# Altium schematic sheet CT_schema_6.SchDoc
size 350 x 348 mm
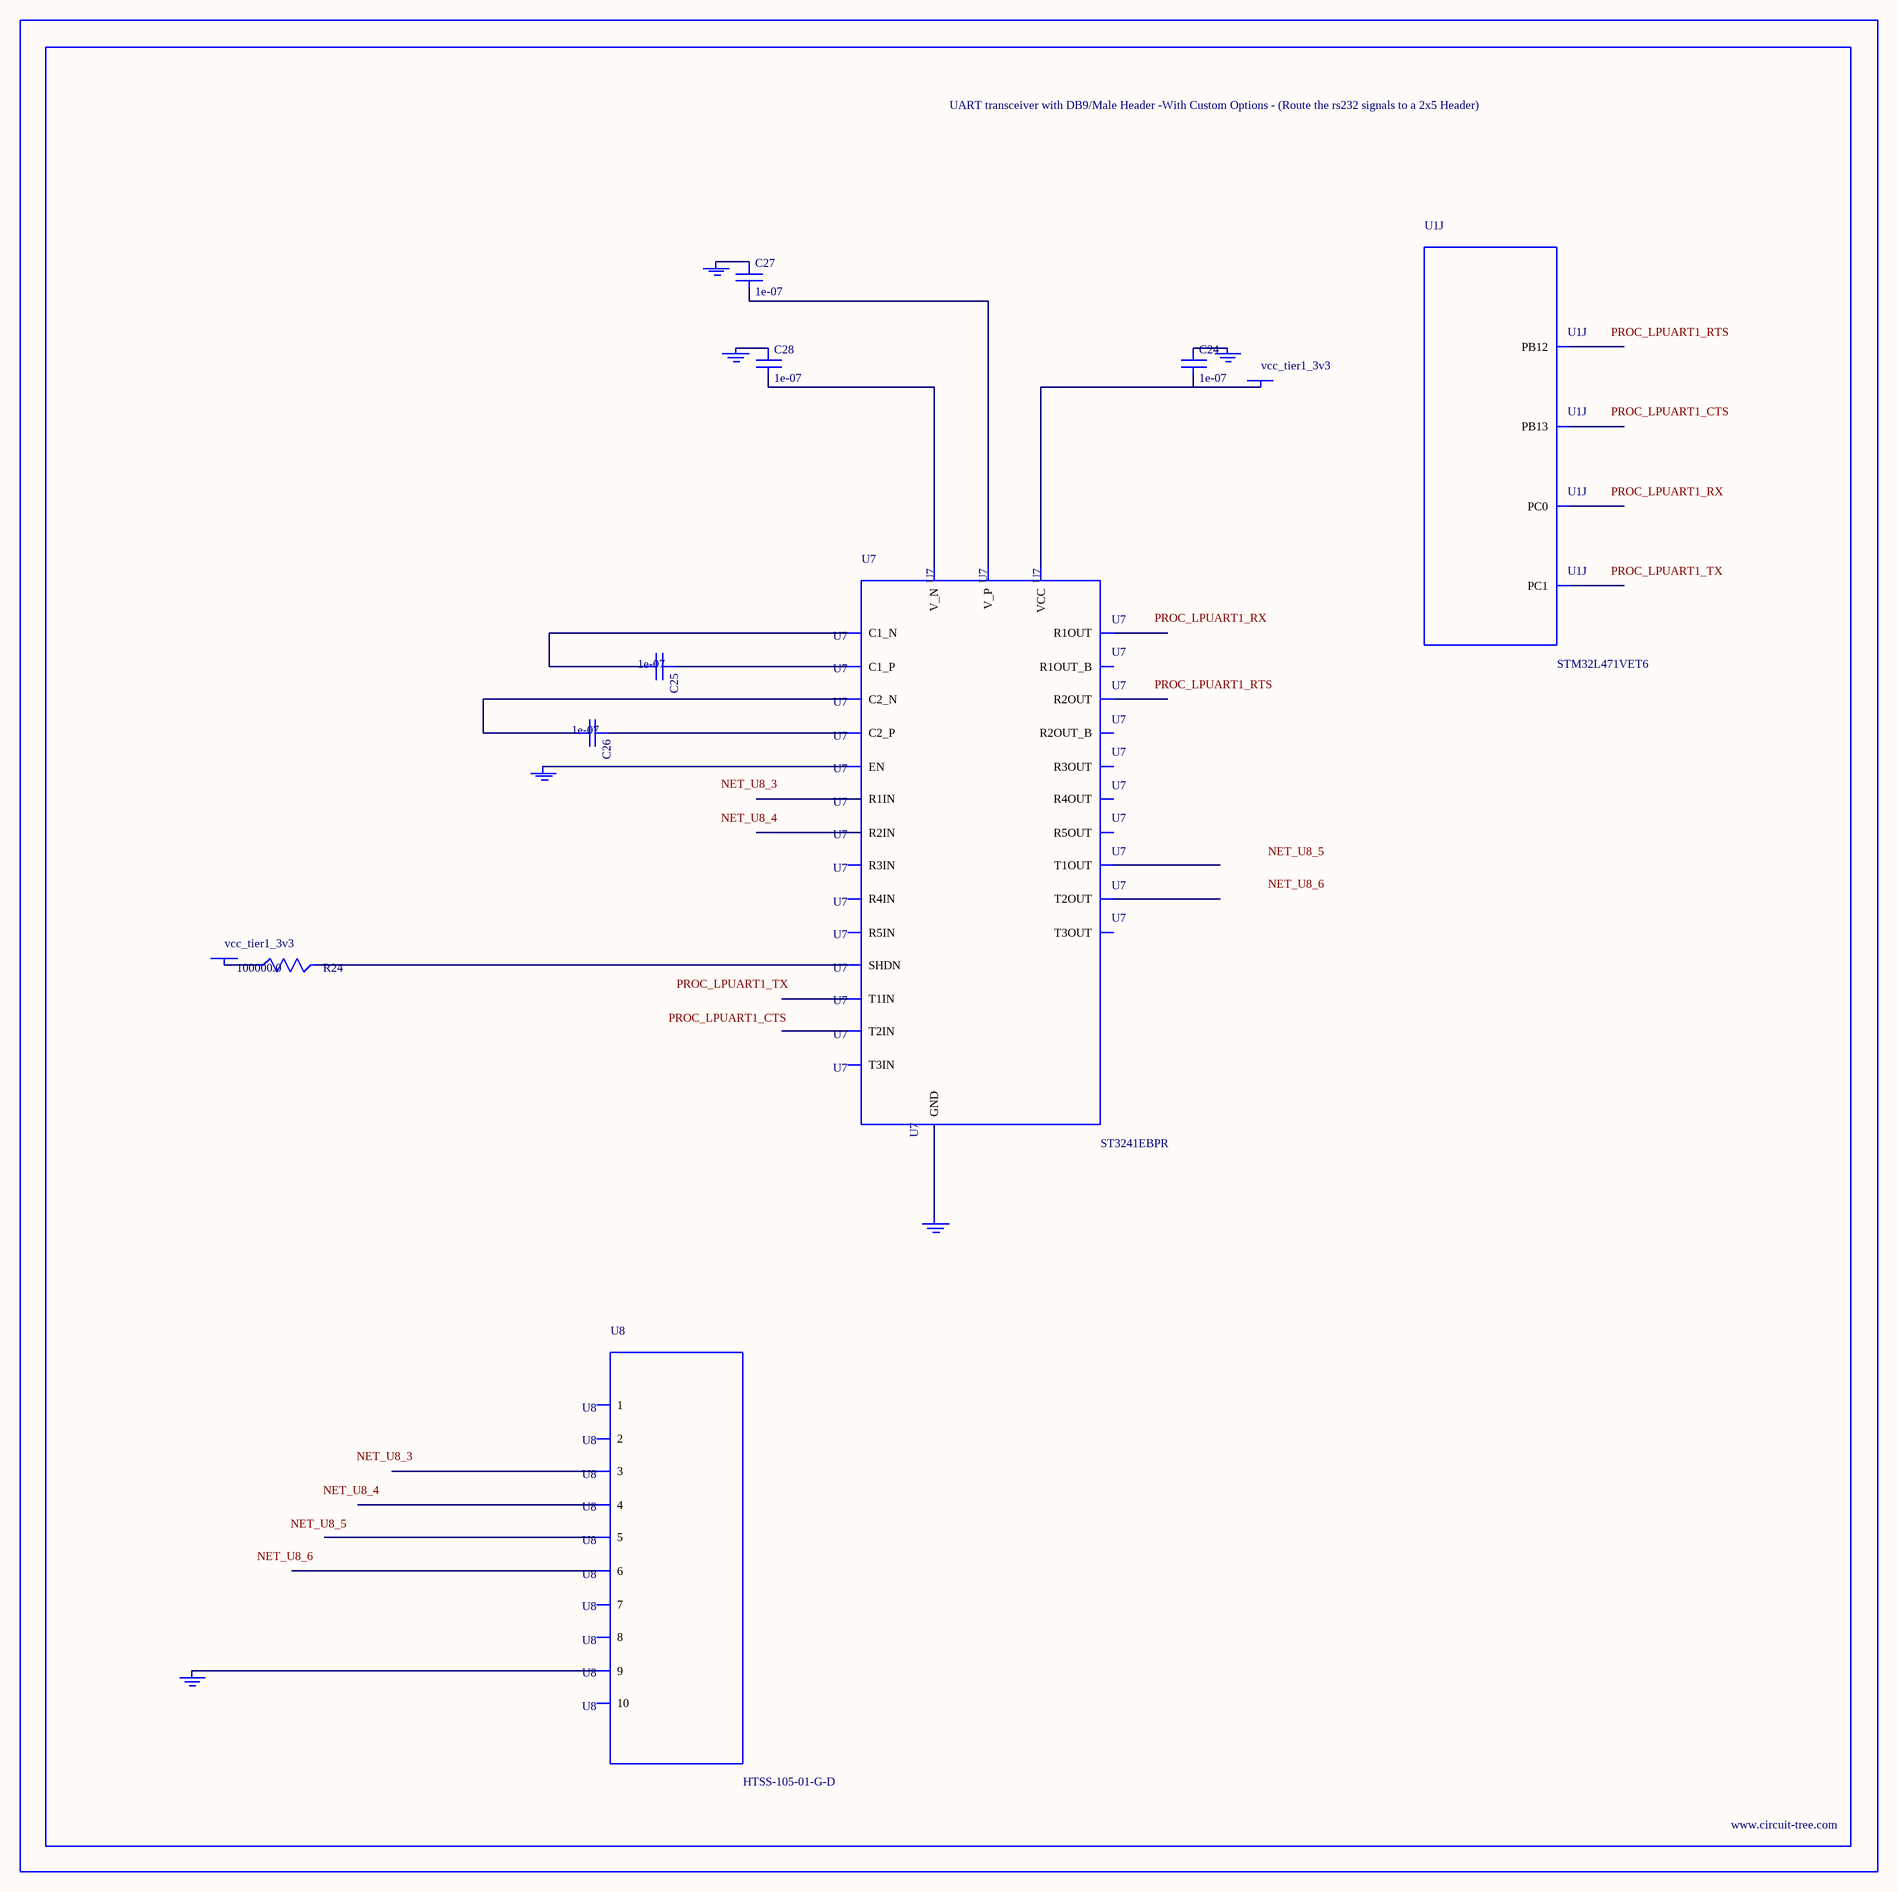
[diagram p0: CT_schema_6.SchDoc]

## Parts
BORDER5  (no value)
C24  1e-07  [C0402]
C25  1e-07  [C0402]
C26  1e-07  [C0402]
C27  1e-07  [C0402]
C28  1e-07  [C0402]
GND_INSTANCE_5_0  (no value)
GND_INSTANCE_5_1  (no value)
GND_INSTANCE_5_2  (no value)
GND_INSTANCE_5_3  (no value)
GND_INSTANCE_5_4  (no value)
GND_INSTANCE_5_5  (no value)
POWER_INSTANCE_5_0  vcc_tier1_3v3
POWER_INSTANCE_5_1  vcc_tier1_3v3
R24  100000.0  [R0603]
U1  STM32L471VET6  [LQFP100]  (part J of 11)
U7  ST3241EBPR  [SSOP-28]
U8  HTSS-105-01-G-D  [HTSS-105-01-G-D]

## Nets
NetC24_1: C24.1 GND_INSTANCE_5_2.0(GND)
NetC24_2: C24.2 POWER_INSTANCE_5_1.0(PWR) U7.26(VCC)
NetC25_1: C25.1 U7.28(C1_P)
NetC25_2: C25.2 U7.24(C1_N)
NetC26_1: C26.1 U7.1(C2_P)
NetC26_2: C26.2 U7.2(C2_N)
NetC27_1: C27.1 GND_INSTANCE_5_3.0(GND)
NetC27_2: C27.2 U7.27(V_P)
NetC28_1: C28.1 GND_INSTANCE_5_0.0(GND)
NetC28_2: C28.2 U7.3(V_N)
NetGND_INSTANCE_5_1_0: GND_INSTANCE_5_1.0(GND) U7.23(EN)
NetGND_INSTANCE_5_4_0: GND_INSTANCE_5_4.0(GND) U7.25(GND)
NetGND_INSTANCE_5_5_0: GND_INSTANCE_5_5.0(GND) U8.9
NetPOWER_INSTANCE_5_0_0: POWER_INSTANCE_5_0.0(PWR) R24.1
NetR24_2: R24.2 U7.22(SHDN)

Not connected (* = marked no-connect by the designer): U1 15(PC0) 16(PC1) 51(PB12) 52(PB13); U7 4(R1IN) 5(R2IN) 6(R3IN) 7(R4IN) 8(R5IN) 9(T1OUT) 10(T2OUT) 11(T3OUT) 12(T3IN) 13(T2IN) 14(T1IN) 15(R5OUT) 16(R4OUT) 17(R3OUT) 18(R2OUT) 19(R1OUT) 20(R2OUT_B) 21(R1OUT_B); U8 1 2 3 4 5 6 7 8 10

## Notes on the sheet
- Labels drawn without touching a wire or pin: NET_U8_3, NET_U8_4, NET_U8_5, NET_U8_6, PROC_LPUART1_CTS, PROC_LPUART1_RTS, PROC_LPUART1_RX, PROC_LPUART1_TX

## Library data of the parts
BORDER5 = BORDER_PAGE5
C24-C28 = C0402C104K3RACTU
GND_INSTANCE_5_0-GND_INSTANCE_5_5 = GND
POWER_INSTANCE_5_0 POWER_INSTANCE_5_1 = PWR
R24 = RC0603JR-07100KL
